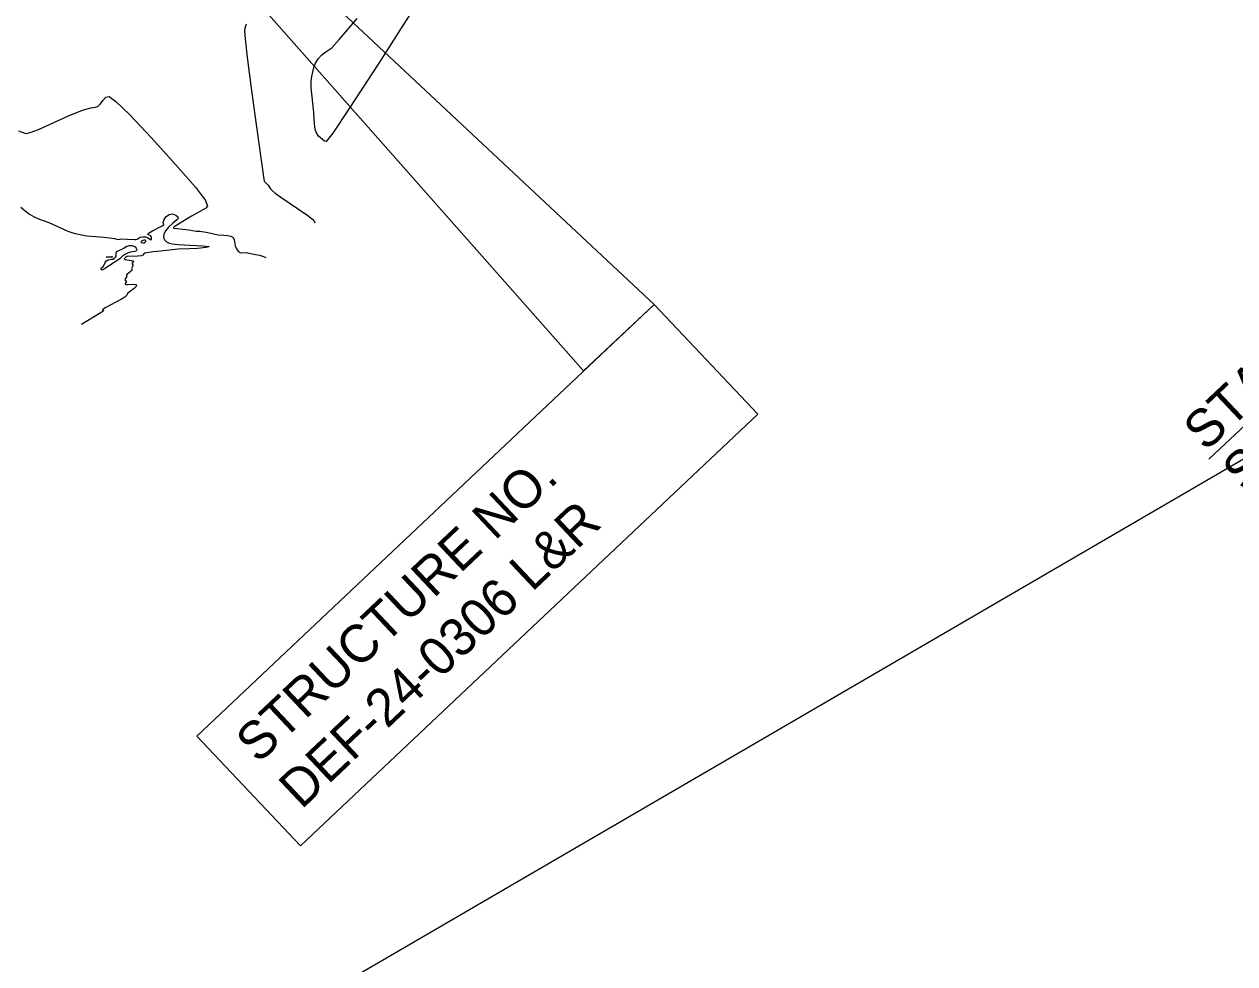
# Model space of a CAD drawing. Extents: x -291892836 to 2945206, y -477993085 to 1832792.
# Drawn here: x 1851534 to 1852737, y 542208 to 543142 of the extents above; entities that cross this region are included whole.
import ezdxf

# ---------------------------------------------------------------- set-up
doc = ezdxf.new("R2010")
doc.units = 0
for name, color, linetype in [('DT_X_Contour_Minor', 7, 'Continuous'), ('Level 40', 7, 'Continuous'), ('SC_Scratch1', 7, 'Continuous')]:
    doc.layers.add(name, color=color, linetype=linetype)

msp = doc.modelspace()

# ---------------------------------------------------------------- linework, layer by layer
at = {"layer": 'DT_X_Contour_Minor'}
for points in [[(1851754.8, 543142.3), (1851753.5, 543138.2), (1851753.2, 543135.4), (1851753.7, 543127.5), (1851755.8, 543109.4), (1851759.9, 543078.5), (1851764.9, 543042.6), (1851772.4, 542988.2), (1851772.8, 542986.2), (1851773.6, 542985.3), (1851776.6, 542982.3), (1851777.7, 542980.7), (1851779.1, 542978.4), (1851780.6, 542976.8), (1851783.6, 542974.3), (1851789.3, 542970.2), (1851816.2, 542952), (1851820.8, 542948.3), (1851822.5, 542946.3), (1851822.9, 542944.8)], [(1851918.1, 543152.7), (1851886.5, 543103.6), (1851857.1, 543058.3), (1851840.8, 543033.8), (1851834.4, 543025.7), (1851832.6, 543025.8), (1851826.7, 543031), (1851825, 543033.5), (1851823.8, 543036.4), (1851823.1, 543039.7), (1851822.5, 543048.1), (1851822, 543054.3), (1851819.5, 543079.2), (1851819.5, 543085.4), (1851820.1, 543090.3), (1851822.1, 543099), (1851823.8, 543103.5), (1851826.3, 543107.8), (1851830, 543111.6), (1851834, 543114.8), (1851839.9, 543118.8), (1851847.4, 543127.4), (1851865.1, 543147.8)], [(1851610, 543063.1), (1851612.7, 543066.8), (1851615.5, 543069.8), (1851618.8, 543070.3), (1851625.4, 543065.5), (1851638.7, 543052.4), (1851660.3, 543029.6), (1851684.6, 543002.9), (1851704.5, 542980.1), (1851714.4, 542966.9), (1851716.4, 542961.2), (1851714.6, 542959.3), (1851700.5, 542951.5), (1851683.3, 542940.9), (1851682.6, 542940.1), (1851682.6, 542939.6), (1851683.3, 542939.4), (1851697.8, 542937.7), (1851705, 542936.6), (1851708.6, 542936.4), (1851715, 542935.5), (1851722.7, 542933.8), (1851726.9, 542933), (1851732.7, 542932.4), (1851736.2, 542932.1), (1851739.5, 542931.5), (1851741.9, 542930.1), (1851743, 542927.8), (1851743.8, 542921.8), (1851745.1, 542919), (1851746.9, 542916.7), (1851748.8, 542915.3), (1851750.5, 542914.9), (1851754.8, 542915.3), (1851764.2, 542913.2), (1851768.2, 542912.5), (1851772, 542911.4), (1851774.4, 542910.4)], [(1851528.7, 543036.3), (1851534.8, 543033.9), (1851536.3, 543033.6), (1851540.2, 543034.4), (1851548.5, 543037.6), (1851578.2, 543051), (1851592, 543056.7), (1851600.6, 543059.1), (1851605, 543059.6), (1851607.5, 543060.3), (1851610, 543063.1)], [(1851530.9, 542960.5), (1851535.1, 542956.7), (1851539.5, 542953.4), (1851544, 542950.8), (1851548.5, 542948.8), (1851558.6, 542945), (1851577.5, 542936.5), (1851583.7, 542934.5), (1851592.7, 542932.5), (1851596.4, 542931.9), (1851613.8, 542930.6), (1851623.9, 542929.3), (1851627.2, 542928.3), (1851629.1, 542928.6), (1851631.2, 542928.9), (1851636.5, 542928.5), (1851643.8, 542928.1), (1851645.3, 542928.2), (1851646.5, 542928.6), (1851648.4, 542930)], [(1851648.4, 542930), (1851649.9, 542930.6), (1851652.2, 542930.9), (1851654.8, 542930.7), (1851657.2, 542930), (1851660.3, 542927.8), (1851660.8, 542928.7), (1851660.8, 542930.3), (1851660, 542931.7), (1851657, 542933.3), (1851657.8, 542934.6), (1851661.7, 542936.9), (1851671.3, 542941.7), (1851672.9, 542942.9), (1851672.3, 542945.2), (1851673.2, 542948), (1851675.2, 542951.1), (1851678.2, 542953.2), (1851681.7, 542953.6), (1851684.9, 542952.5), (1851686.9, 542950.8), (1851687.1, 542949.2), (1851686, 542947.8), (1851681.8, 542944.4), (1851677.7, 542940.3), (1851675, 542937.1), (1851673, 542933.6), (1851672.6, 542930.5), (1851673.6, 542927.8), (1851675.7, 542925.8), (1851678.3, 542924.5), (1851681.1, 542923.8), (1851687.1, 542923.3), (1851699.2, 542922.7), (1851711.9, 542921.9), (1851717.6, 542921.3), (1851718, 542921), (1851717.6, 542920.8), (1851714.9, 542920.1), (1851706.3, 542919.3), (1851698.4, 542918.8), (1851687.1, 542918.5), (1851670.1, 542916.5), (1851662.4, 542915.9), (1851654.2, 542914.6), (1851653.2, 542914), (1851652.2, 542912.6), (1851650.5, 542912), (1851647.2, 542911.7), (1851636.2, 542911.4), (1851635.2, 542910.7), (1851633.4, 542908.9), (1851634.4, 542908.4), (1851642.4, 542907.1), (1851642.8, 542906.4), (1851641.5, 542904.6), (1851641.6, 542903.8), (1851642.4, 542902.1), (1851641.9, 542901.2), (1851640.8, 542899.5), (1851641.4, 542898.1), (1851641.2, 542897.3), (1851638, 542894.8), (1851636.6, 542893.6), (1851636, 542892.7), (1851636, 542891.2), (1851634.1, 542888.3), (1851634.6, 542887.7), (1851635.9, 542886.8), (1851635.7, 542886.2), (1851634.5, 542884.6), (1851634.4, 542883.9), (1851635.1, 542883.5), (1851636.9, 542883.4), (1851642.8, 542883.7), (1851645.1, 542883.4), (1851645.8, 542882.5), (1851645.1, 542881.1), (1851643.4, 542879.5), (1851637.2, 542874.9), (1851635.9, 542872.4), (1851634.2, 542870.9), (1851630.8, 542868.8), (1851614.7, 542860.3), (1851612, 542858.3), (1851612, 542858), (1851613.1, 542857.6), (1851612.8, 542857), (1851610.7, 542855.5), (1851591.3, 542843.6)], [(1851654.4, 542927.8), (1851654.8, 542926.6), (1851654.9, 542925.8), (1851654.4, 542925.1), (1851653.3, 542924.7), (1851652, 542924.7), (1851650.9, 542925), (1851650.6, 542925.8), (1851651, 542926.6), (1851651.6, 542927.3), (1851653.3, 542927.9), (1851654.4, 542927.8)], [(1851611.3, 542900.2), (1851611.9, 542900.3), (1851612.4, 542900.6), (1851613, 542901.6), (1851614.8, 542905.4), (1851616.1, 542907.1), (1851617.8, 542908.1), (1851621.1, 542908.5), (1851622.6, 542908.6), (1851624, 542909.6), (1851624.9, 542910.5), (1851625.5, 542911.7), (1851625.7, 542914.2), (1851625.8, 542915.9), (1851626.4, 542916.4), (1851633.3, 542919.7), (1851635.7, 542921.2), (1851638.4, 542922.1), (1851639.9, 542922.3), (1851641.5, 542922.1), (1851643.1, 542921.7), (1851644.5, 542920.8), (1851645.6, 542919.5), (1851646.2, 542918.2), (1851645.8, 542917), (1851644.3, 542916.4), (1851639.8, 542915.7), (1851637.6, 542915), (1851634.2, 542913.3), (1851632.3, 542911.9), (1851629.2, 542909), (1851623.6, 542905.3), (1851615.9, 542900.4), (1851614.8, 542899.4), (1851612.3, 542898.2), (1851611.2, 542897.9), (1851610.8, 542898.3), (1851610.8, 542898.9), (1851611.3, 542900.2)], [(1851615.6, 542910.7), (1851621, 542911.3), (1851621.7, 542911.4), (1851621.9, 542910.8), (1851621.8, 542910.6), (1851615.6, 542910.7)]]:
    msp.add_lwpolyline(points, dxfattribs=at)
at = {"layer": 'Level 40'}
msp.add_line((1852711.5, 542709.9), (1853310.4, 543275.2), dxfattribs=at)
for points in [[(1852160.3, 542863.7), (1851416.4, 543559.9), (1852090.1, 542797.5)], [(1851705.7, 542434.7), (1852160.3, 542863.7), (1852263.2, 542754.6), (1851808.7, 542325.6)]]:
    msp.add_lwpolyline(points, close=True, dxfattribs=at)
at = {"layer": 'SC_Scratch1'}
msp.add_lwpolyline([(1847508.1, 542206.7), (1846998.9, 543896.8), (1851573.8, 547209.2), (1853501.8, 547291.7), (1855222.4, 545290.6), (1854278.6, 544392.1), (1853736.4, 543286.9), (1848894.1, 540466.9), (1848705.9, 540646.3)], close=True, dxfattribs=at)

# ---------------------------------------------------------------- texts
at = {"layer": 'Level 40'}
for s, p in [('STA. 64+88.39 S.R. 424 =', (1852708.4, 542716.6)), ('STA. 1909+61.43 RAMP "C"', (1852747.1, 542675.7)), ('STRUCTURE NO.', (1851766.8, 542406.4)), ('DEF-24-0306 L&R', (1851809.7, 542361))]:
    msp.add_text(s, height=37.5, rotation=43.3446, dxfattribs=at).set_placement(p)

doc.saveas('drawing.dxf')
